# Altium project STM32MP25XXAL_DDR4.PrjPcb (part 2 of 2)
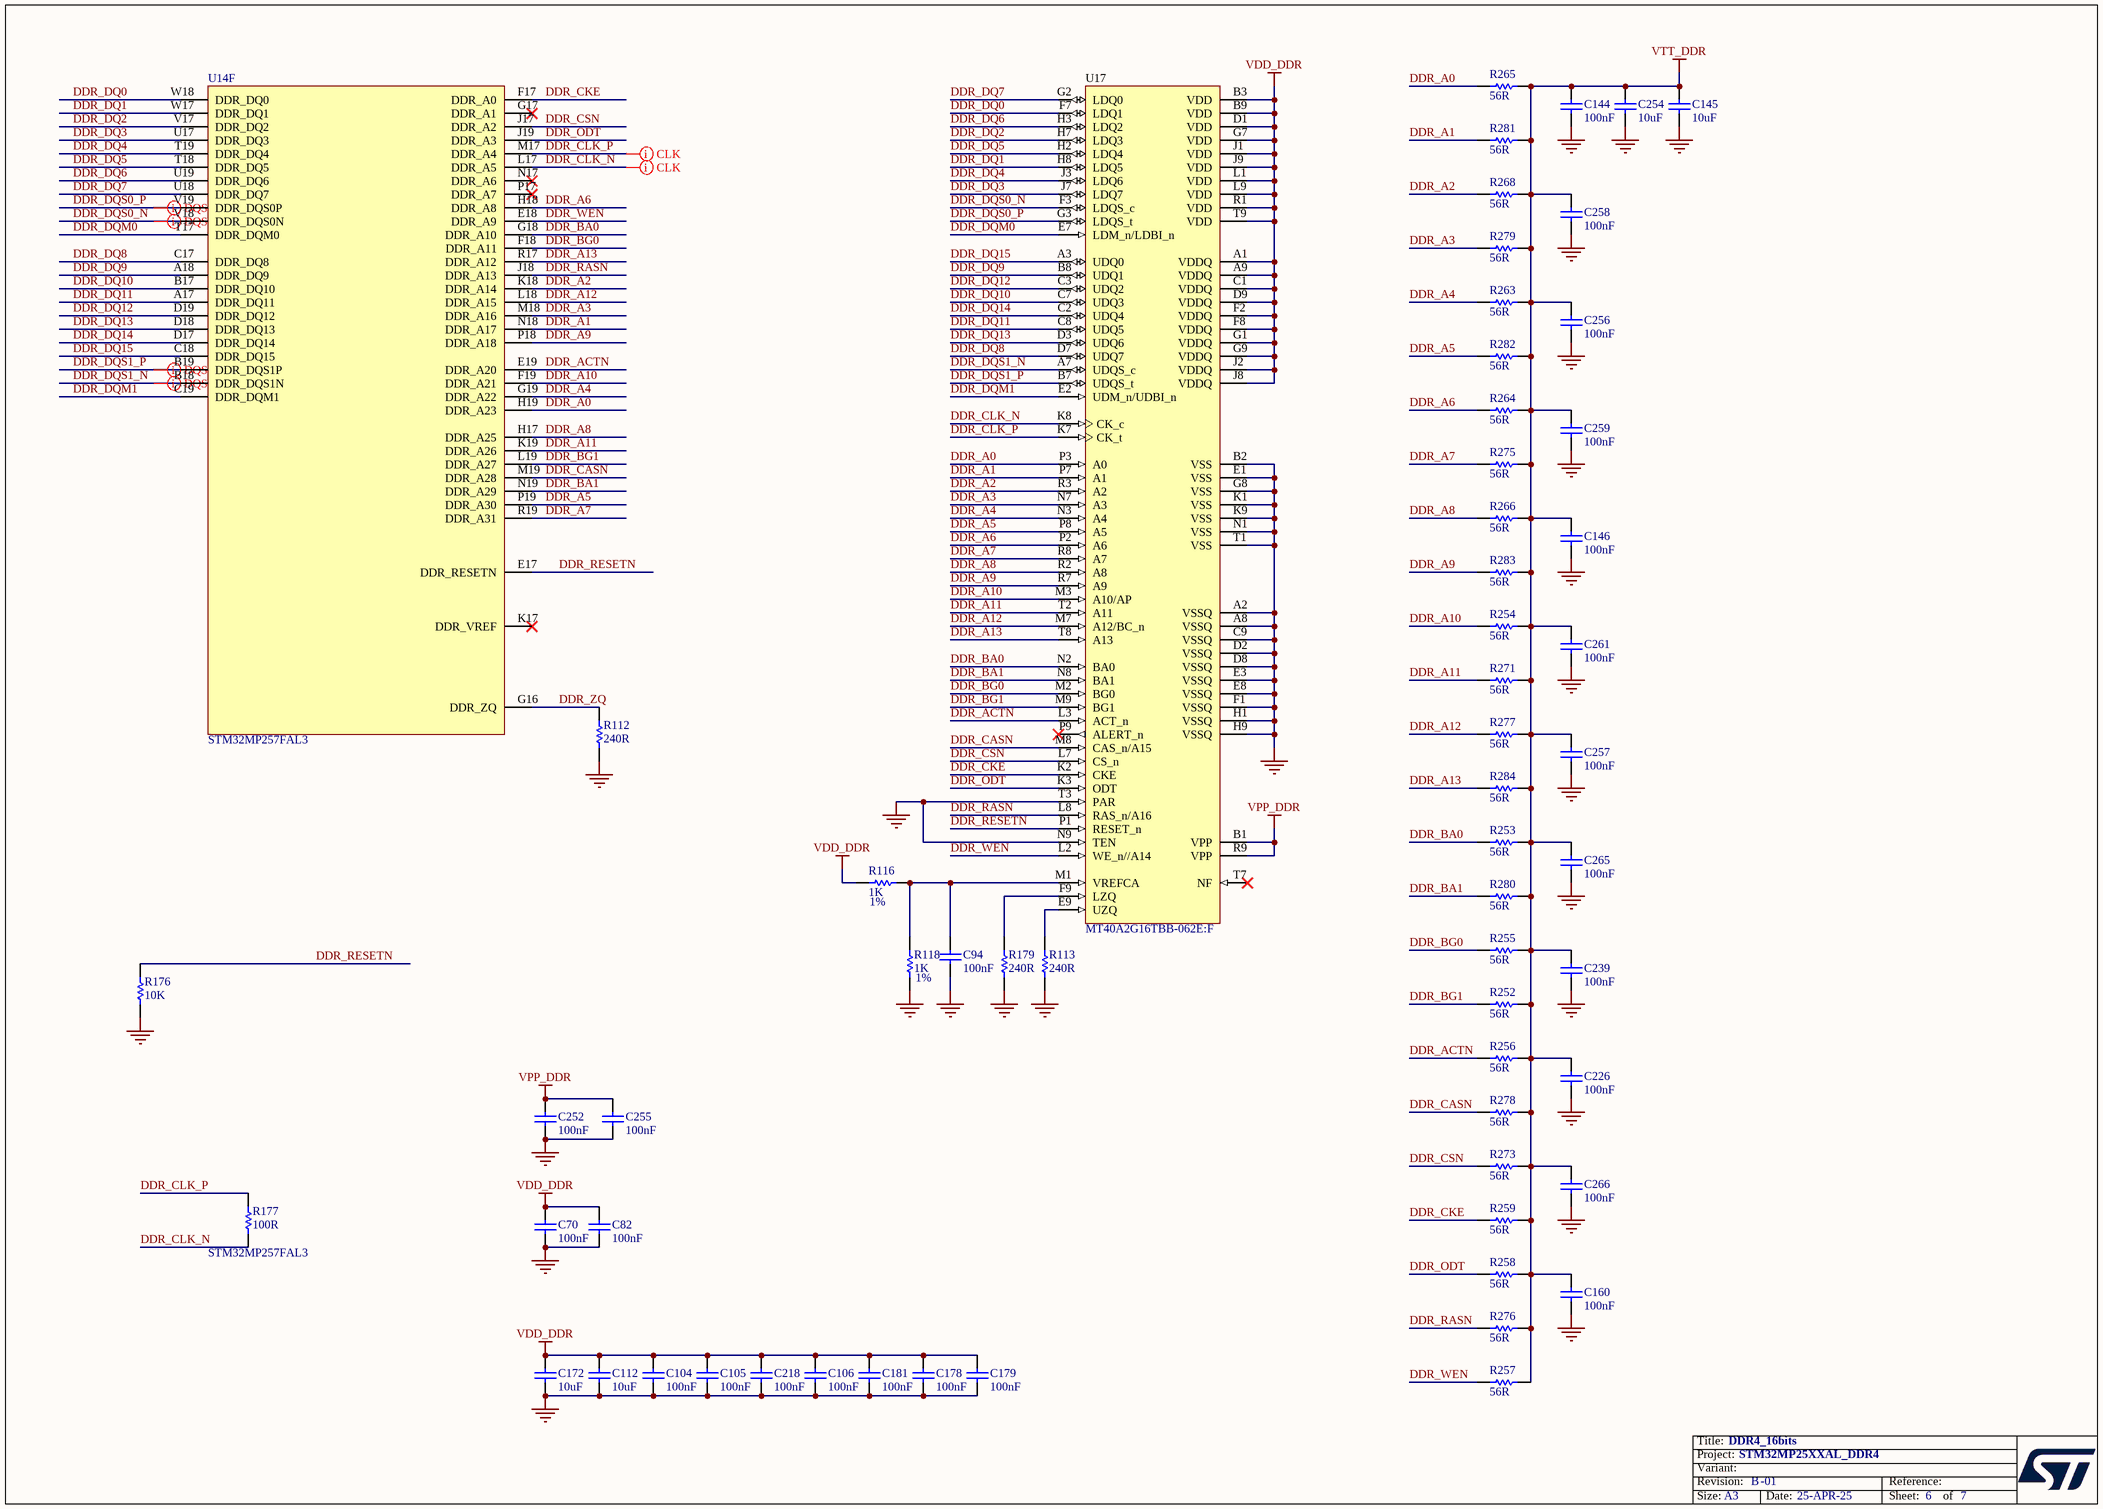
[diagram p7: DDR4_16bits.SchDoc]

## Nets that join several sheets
1V8: PMIC (5 pins), STM32MP25XXAL Power (20 pins), eMMC (11 pins)
GND: STM32MP25XXAL I_Os (7 pins), PMIC (62 pins), STM32MP25XXAL Power (94 pins), eMMC (17 pins), DDR4_16bits (52 pins)
VDD3V3_USB: PMIC (C156.2 U26.13), STM32MP25XXAL Power (R286.1)
VDD_DDR: PMIC (7 pins), STM32MP25XXAL Power (12 pins), DDR4_16bits (32 pins)
VDD_EMMC: PMIC (C190.1 U26.16), eMMC (6 pins)
VDDA1V8_AON: STM32MP25XXAL I_Os (U14.N1), PMIC (C189.2 U26.14), STM32MP25XXAL Power (C234.2 U14.N5)
VDDCORE: PMIC (6 pins), STM32MP25XXAL Power (21 pins)
VDDCPU: PMIC (5 pins), STM32MP25XXAL Power (10 pins)
VDDGPU: PMIC (6 pins), STM32MP25XXAL Power (10 pins)
VDDIO: STM32MP25XXAL I_Os (R27.2 R260.2 R261.2), PMIC (6 pins), STM32MP25XXAL Power (13 pins)
VDDIO_SDCARD: PMIC (C217.1 U26.2), STM32MP25XXAL Power (C210.2 U14.D10)
VPP_DDR: PMIC (C91.1 U26.7), DDR4_16bits (C252.2 C255.2 U17.B1 U17.R9)
VTT_DDR: PMIC (C40.2 U26.44), DDR4_16bits (39 pins)
eMMC.SDMMC2_CK: STM32MP25XXAL I_Os (U14.G14), eMMC (R103.1 U37.M6)
eMMC.SDMMC2_CMD: STM32MP25XXAL I_Os (U14.D14), eMMC (R104.1 U37.M5)
eMMC.SDMMC2_D0: STM32MP25XXAL I_Os (U14.A16), eMMC (R101.1 U37.A3)
eMMC.SDMMC2_D1: STM32MP25XXAL I_Os (U14.B16), eMMC (U37.A4)
eMMC.SDMMC2_D2: STM32MP25XXAL I_Os (U14.B15), eMMC (U37.A5)
eMMC.SDMMC2_D3: STM32MP25XXAL I_Os (U14.C16), eMMC (U37.B2)
eMMC.SDMMC2_D4: STM32MP25XXAL I_Os (U14.D15), eMMC (U37.B3)
eMMC.SDMMC2_D5: STM32MP25XXAL I_Os (U14.F15), eMMC (U37.B4)
eMMC.SDMMC2_D6: STM32MP25XXAL I_Os (U14.F14), eMMC (U37.B5)
eMMC.SDMMC2_D7: STM32MP25XXAL I_Os (U14.C15), eMMC (U37.B6)
I2C7.SCL: STM32MP25XXAL I_Os (R261.1 U14.A11), PMIC (U26.33)
I2C7.SDA: STM32MP25XXAL I_Os (R260.1 U14.A13), PMIC (U26.34)
MP257_WAKEUP: STM32MP25XXAL I_Os (U14.P15), PMIC (U26.32)
NRST: STM32MP25XXAL I_Os (C33.2 U14.N2), PMIC (R81.1)
NRSTC1MS: STM32MP25XXAL I_Os (R27.1 R272.1 U14.T1), PMIC (R59.1), eMMC (D7.2)
PMIC_WAKEUPn: STM32MP25XXAL I_Os (U14.P4), PMIC (R46.1)
PWR_CPU_ON: STM32MP25XXAL I_Os (R272.2 U14.P2), PMIC (R60.1)
PWR_ON: STM32MP25XXAL I_Os (U14.U3), PMIC (R2.1)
